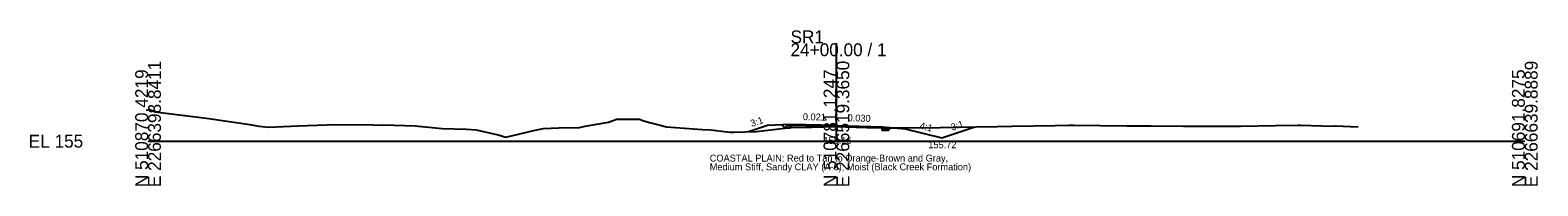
# Model space of a CAD drawing. Extents: x -1079 to 303, y -11 to 4017.
# Drawn here: x -25.7 to 302.8, y 2990.3 to 3024.1 of the extents above; entities that cross this region are included whole.
import ezdxf

# ---------------------------------------------------------------- set-up
doc = ezdxf.new("R2010")
doc.units = 0
for name, color, linetype in [('Default', 7, 'Continuous'), ('Exist Cross Section Cell', 7, 'Continuous'), ('Exist XS Center Line Elevation Label', 7, 'Continuous'), ('Exist XS Ground Line', 7, 'Continuous'), ('Prop CMT Pvmt Course 1', 7, 'Continuous'), ('Prop CMT Pvmt Course 2', 7, 'Continuous'), ('Prop CMT Pvmt Course 3', 7, 'Continuous'), ('Prop CMT Pvmt Surface', 7, 'Continuous'), ('Prop CMT Pvmt Surface Shoulder', 7, 'Continuous'), ('Prop CMT Shld Paved Course 1', 7, 'Continuous'), ('Prop CMT Shld Paved Course 2', 7, 'Continuous'), ('Prop CMT Shld Paved Course 3', 7, 'Continuous'), ('Prop CMT Slope Grass', 7, 'Continuous'), ('Prop CMT Subgrade Earthwork', 7, 'Continuous'), ('Prop Road Sect_ Material - Tx (Composite Desc)', 7, 'Continuous'), ('Prop XS Ditch Standard Text', 7, 'Continuous'), ('Prop XS SE Text', 7, 'Continuous'), ('Prop XS Side Slope Text', 7, 'Continuous')]:
    doc.layers.add(name, color=color, linetype=linetype)

msp = doc.modelspace()

# ---------------------------------------------------------------- linework, layer by layer
at = {"layer": 'Exist Cross Section Cell'}
for p, q in [((150, 3000), (150, 3021.28)), ((0, 3000), (150, 3000)), ((150, 3000), (300, 3000))]:
    msp.add_line(p, q, dxfattribs=at)
at = {"layer": 'Exist XS Ground Line'}
msp.add_lwpolyline([(0, 3007.09), (0.66, 3006.78), (1.57, 3006.4), (13.25, 3004.96), (22.18, 3003.64), (24.11, 3003.29), (26.22, 3003.05), (32.68, 3003.32), (38.91, 3003.59), (40.87, 3003.65), (49.03, 3003.52), (50.83, 3003.51), (51.36, 3003.52), (58.18, 3003.37), (64.06, 3002.78), (69.4, 3002.61), (71.51, 3002.48), (76.29, 3001.37), (77.94, 3000.88), (84.32, 3002.39), (86.17, 3002.79), (89.52, 3002.88), (94, 3002.97), (95.28, 3003.26), (100.31, 3004.11), (101.33, 3004.48), (102.1, 3004.76), (102.75, 3004.76), (107.07, 3004.77), (107.84, 3004.53), (109.27, 3004.07), (111.61, 3003.49), (113, 3003.14), (120.81, 3002.57), (122.65, 3002.44), (126.18, 3002), (126.76, 3001.93), (127.54, 3001.96), (132.58, 3002.1), (139.99, 3002.99), (144.69, 3003.07), (149.75, 3003.16), (156.62, 3003.01), (160.29, 3002.93), (164.99, 3002.89), (172.58, 3002.98), (175.83, 3003.04), (185, 3003.17), (188.28, 3003.25), (197.64, 3003.43), (200.72, 3003.47), (201.8, 3003.46), (213.17, 3003.35), (218.6, 3003.35), (225.62, 3003.26), (235.4, 3003.24), (238.06, 3003.25), (245.69, 3003.39), (250.51, 3003.47), (251.17, 3003.49), (255.79, 3003.32), (258.44, 3003.3), (258.76, 3003.33), (263.69, 3003.15)], dxfattribs=at)
at = {"layer": 'Prop CMT Pvmt Course 1'}
for points in [[(150, 3003.42), (140, 3003.63)], [(140, 3003.63), (140, 3003.38), (140, 3003.38), (140, 3003.51)], [(140, 3003.51), (150, 3003.29)], [(150, 3003.17), (150, 3003.42)], [(150, 3003.42), (160, 3003.12)], [(150, 3003.17), (150, 3003.42)], [(150, 3003.29), (150, 3003.17), (150, 3003.17)], [(160, 3002.99), (150, 3003.29)], [(150, 3003.29), (150, 3003.17), (150, 3003.17)], [(160, 3003.12), (160, 3002.87), (160, 3002.87), (160, 3002.99)]]:
    msp.add_lwpolyline(points, dxfattribs=at)
at = {"layer": 'Prop CMT Pvmt Course 2'}
for points in [[(140, 3003.38), (140, 3003.38), (140, 3003.38)], [(160, 3002.87), (160, 3002.87), (160, 3002.87)]]:
    msp.add_lwpolyline(points, close=True, dxfattribs=at)
for points in [[(140, 3003.38), (140, 3003.38)], [(160, 3002.87), (160, 3002.87)]]:
    msp.add_lwpolyline(points, dxfattribs=at)
at = {"layer": 'Prop CMT Pvmt Course 3'}
for points in [[(140, 3003.38), (140, 3003.38), (140, 3002.88), (140, 3002.88)], [(140, 3002.88), (140, 3003.38)], [(160, 3002.87), (160, 3002.87), (160, 3002.37), (160, 3002.37)], [(160, 3002.37), (160, 3002.87)]]:
    msp.add_lwpolyline(points, dxfattribs=at)
at = {"layer": 'Prop CMT Pvmt Surface'}
for q in [(140, 3003.63), (160, 3003.12)]:
    msp.add_line((150, 3003.42), q, dxfattribs=at)
at = {"layer": 'Prop CMT Pvmt Surface Shoulder'}
for p, q in [((140, 3003.63), (140, 3003.63)), ((160, 3003.12), (160, 3003.12))]:
    msp.add_line(p, q, dxfattribs=at)
at = {"layer": 'Prop CMT Shld Paved Course 1'}
for points in [[(140, 3003.63), (140, 3003.63), (139.75, 3003.39)], [(139.75, 3003.39), (140, 3003.38)], [(140, 3003.38), (140, 3003.63)], [(160, 3003.12), (160, 3003.12), (160.26, 3002.86)], [(160, 3002.87), (160, 3003.12)], [(160.26, 3002.86), (160, 3002.87)]]:
    msp.add_lwpolyline(points, dxfattribs=at)
at = {"layer": 'Prop CMT Shld Paved Course 2'}
for points in [[(140, 3003.38), (139.75, 3003.39)], [(139.75, 3003.39), (139.75, 3003.39)], [(139.75, 3003.39), (140, 3003.38)], [(140, 3003.38), (140, 3003.38)], [(160, 3002.87), (160.26, 3002.86)], [(160.26, 3002.86), (160, 3002.87)], [(160, 3002.87), (160, 3002.87)], [(160.26, 3002.86), (160.26, 3002.86)]]:
    msp.add_lwpolyline(points, dxfattribs=at)
at = {"layer": 'Prop CMT Shld Paved Course 3'}
for points in [[(140, 3003.38), (139.75, 3003.39), (139.25, 3003.4), (138.76, 3002.91)], [(138.76, 3002.91), (140, 3002.88)], [(140, 3002.88), (140, 3003.38)], [(160, 3002.87), (160.26, 3002.86), (160.76, 3002.85), (161.27, 3002.33)], [(160, 3002.37), (160, 3002.87)], [(161.27, 3002.33), (160, 3002.37)]]:
    msp.add_lwpolyline(points, dxfattribs=at)
at = {"layer": 'Prop CMT Slope Grass'}
for p, q in [((135, 3003.44), (130.84, 3002.05)), ((140, 3003.63), (135, 3003.44)), ((160, 3003.12), (165, 3002.72)), ((173, 3000.72), (180.15, 3003.1)), ((165, 3002.72), (173, 3000.72))]:
    msp.add_line(p, q, dxfattribs=at)
at = {"layer": 'Prop CMT Subgrade Earthwork'}
for points in [[(138.76, 3002.91), (138.11, 3003.56)], [(140, 3002.88), (138.76, 3002.91)], [(140, 3002.88), (140, 3002.99)], [(140, 3002.88), (140, 3002.88)], [(160, 3002.37), (160, 3002.94)], [(161.27, 3002.33), (161.91, 3002.97)], [(160, 3002.37), (161.27, 3002.33)], [(160, 3002.37), (160, 3002.37)]]:
    msp.add_lwpolyline(points, dxfattribs=at)

# ---------------------------------------------------------------- texts
at = {"layer": 'Default'}
msp.add_text('-', height=0.0001, dxfattribs=at).set_placement((0, 3000))
at = {"layer": 'Exist Cross Section Cell'}
for s, p in [('SR1', (140, 3021.28)), ('24+00.00 / 1', (140, 3018.48)), ('EL 155', (-26, 2998.6))]:
    msp.add_text(s, height=2.8, dxfattribs=at).set_placement(p)
for s, p in [('E 2266398.8411', (2.8, 2990)), ('E 2266519.3650', (152.8, 2990)), ('E 2266639.8889', (302.8, 2990)), ('N 510870.4219', (0, 2990)), ('N 510781.1247', (150, 2990)), ('N 510691.8275', (300, 2990))]:
    msp.add_text(s, height=2.8, rotation=90, dxfattribs=at).set_placement(p)
at = {"layer": 'Exist XS Center Line Elevation Label'}
msp.add_text('158.16', height=1.5, dxfattribs=at).set_placement((147.16, 2999.41))
at = {"layer": 'Prop Road Sect_ Material - Tx (Composite Desc)'}
for s, p in [('COASTAL PLAIN: Red to Tan to Orange-Brown and Gray, ', (122.39, 2995.57)), ('Medium Stiff, Sandy CLAY (A-6), Moist (Black Creek Formation)', (122.39, 2993.67))]:
    msp.add_text(s, height=1.5, dxfattribs=at).set_placement(p)
at = {"layer": 'Prop XS Ditch Standard Text'}
msp.add_text('155.72', height=1.5, dxfattribs=at).set_placement((170.02, 2998.47))
at = {"layer": 'Prop XS SE Text'}
for s, rotation, p in [('0.021', 358.7724, (142.67, 3004.58)), ('0.030', 358.2816, (152.41, 3004.35))]:
    msp.add_text(s, height=1.5, rotation=rotation, dxfattribs=at).set_placement(p)
at = {"layer": 'Prop XS Side Slope Text'}
for s, rotation, p in [('3:1', 18.4332, (131.55, 3003.08)), ('4:1', 345.9638, (168.03, 3002.73)), ('3:1', 18.4332, (175.21, 3002.25))]:
    msp.add_text(s, height=1.5, rotation=rotation, dxfattribs=at).set_placement(p)

doc.saveas('drawing.dxf')
